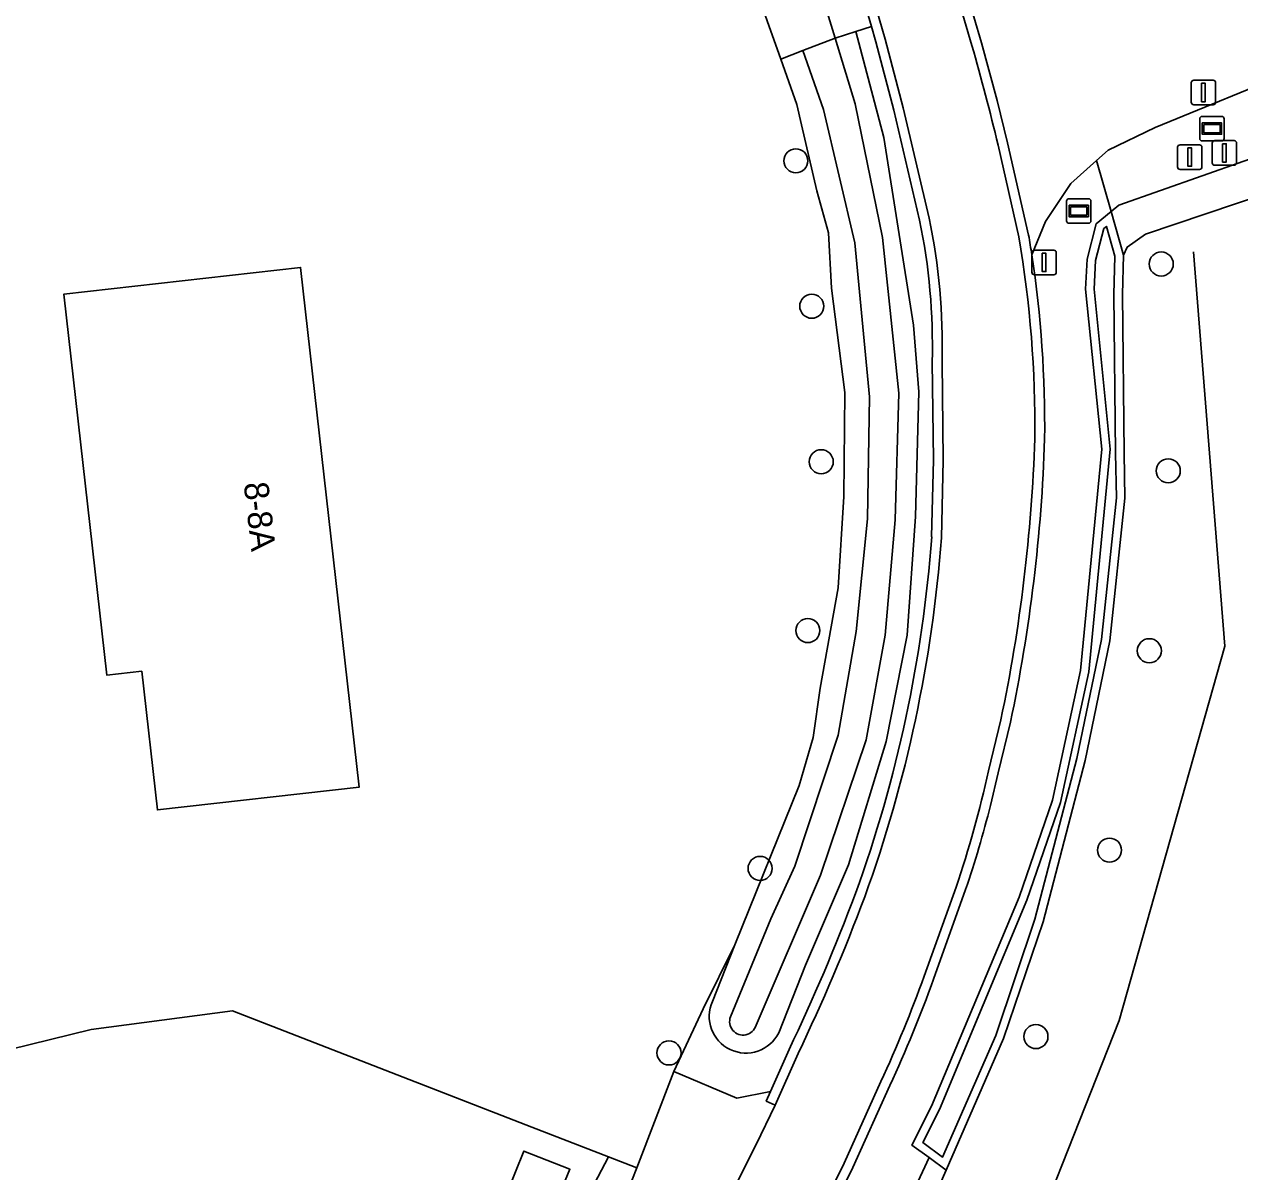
# Model space of a CAD drawing. Extents: x 162510 to 163918, y 388494 to 389774.
# Drawn here: x 163242.06 to 163291.5, y 389283.89 to 389330.57 of the extents above; entities that cross this region are included whole.
import ezdxf

# ---------------------------------------------------------------- set-up
doc = ezdxf.new("R2010")
doc.units = 0
for name, color, linetype in [('IMGEO_Afsluitpaal', 7, 'Continuous'), ('IMGEO_Boom', 7, 'Continuous'), ('IMGEO_Duiker', 7, 'Continuous'), ('IMGEO_Erf', 7, 'Continuous'), ('IMGEO_Grasland_agrarisch', 7, 'Continuous'), ('IMGEO_Grasland_overig', 7, 'Continuous'), ('IMGEO_Hek', 7, 'Continuous'), ('IMGEO_Informatiebord', 7, 'Continuous'), ('IMGEO_Lichtmast', 7, 'Continuous'), ('IMGEO_Oever', 7, 'Continuous'), ('IMGEO_Pand', 7, 'Continuous'), ('IMGEO_Pand_nummerreeks', 7, 'Continuous'), ('IMGEO_Rijbaan_lokaal_gesloten', 7, 'Continuous'), ('IMGEO_Rijbaan_lokaal_halfverhard', 7, 'Continuous'), ('IMGEO_Rijbaan_lokaal_onverhard', 7, 'Continuous'), ('IMGEO_Waterloop', 7, 'Continuous'), ('IMGEO_Wegwijzer', 7, 'Continuous')]:
    doc.layers.add(name, color=color, linetype=linetype)

msp = doc.modelspace()

# ---------------------------------------------------------------- linework, layer by layer
at = {"layer": 'IMGEO_Afsluitpaal'}
for p, q in [((163289.633, 389328.291), (163290.423, 389328.291)), ((163290.423, 389328.291), (163289.633, 389328.291)), ((163289.533, 389327.391), (163289.533, 389328.191)), ((163289.533, 389328.191), (163289.533, 389327.391)), ((163290.523, 389328.191), (163290.523, 389327.391)), ((163290.523, 389327.391), (163290.523, 389328.191)), ((163290.423, 389327.291), (163289.633, 389327.291)), ((163289.633, 389327.291), (163290.423, 389327.291)), ((163290.485, 389325.832), (163291.275, 389325.832)), ((163291.275, 389325.832), (163290.485, 389325.832)), ((163288.975, 389324.762), (163288.975, 389325.562)), ((163288.975, 389325.562), (163288.975, 389324.762)), ((163289.075, 389325.662), (163289.865, 389325.662)), ((163289.865, 389325.662), (163289.075, 389325.662)), ((163289.965, 389325.562), (163289.965, 389324.762)), ((163289.965, 389324.762), (163289.965, 389325.562)), ((163290.385, 389324.932), (163290.385, 389325.732)), ((163290.385, 389325.732), (163290.385, 389324.932)), ((163291.375, 389325.732), (163291.375, 389324.932)), ((163291.375, 389324.932), (163291.375, 389325.732)), ((163291.275, 389324.832), (163290.485, 389324.832)), ((163290.485, 389324.832), (163291.275, 389324.832)), ((163289.865, 389324.662), (163289.075, 389324.662)), ((163289.075, 389324.662), (163289.865, 389324.662))]:
    msp.add_line(p, q, dxfattribs=at)
for points in [[(163289.953, 389328.166), (163290.103, 389328.166), (163290.103, 389327.416), (163289.953, 389327.416), (163289.953, 389328.166)], [(163289.395, 389325.537), (163289.545, 389325.537), (163289.545, 389324.787), (163289.395, 389324.787), (163289.395, 389325.537)], [(163290.805, 389325.707), (163290.955, 389325.707), (163290.955, 389324.957), (163290.805, 389324.957), (163290.805, 389325.707)]]:
    msp.add_lwpolyline(points, dxfattribs=at)
for centre, start, end in [((163289.633, 389328.191), 90, 180), ((163289.633, 389328.191), 90, 180), ((163290.423, 389328.191), 0, 90), ((163290.423, 389328.191), 360, 90), ((163289.633, 389327.391), 180, 270), ((163289.633, 389327.391), 180, 270), ((163290.423, 389327.391), 270, 0), ((163290.423, 389327.391), 270, 0), ((163290.485, 389325.732), 90, 180), ((163290.485, 389325.732), 90, 180), ((163291.275, 389325.732), 0, 90), ((163291.275, 389325.732), 360, 90), ((163289.075, 389325.562), 90, 180), ((163289.075, 389325.562), 90, 180), ((163289.865, 389325.562), 0, 90), ((163289.865, 389325.562), 360, 90), ((163290.485, 389324.932), 180, 270), ((163290.485, 389324.932), 180, 270), ((163291.275, 389324.932), 270, 0), ((163291.275, 389324.932), 270, 0), ((163289.075, 389324.762), 180, 270), ((163289.075, 389324.762), 180, 270), ((163289.865, 389324.762), 270, 0), ((163289.865, 389324.762), 270, 0)]:
    msp.add_arc(centre, 0.1, start, end, dxfattribs=at)
at = {"layer": 'IMGEO_Boom'}
for centre in [(163273.447, 389325.011), (163288.31, 389320.814), (163274.093, 389319.095), (163274.479, 389312.769), (163288.596, 389312.401), (163273.936, 389305.901), (163287.825, 389305.08), (163286.207, 389296.968), (163271.992, 389296.225), (163283.213, 389289.383), (163268.286, 389288.718)]:
    msp.add_circle(centre, 0.489, dxfattribs=at)
at = {"layer": 'IMGEO_Duiker'}
msp.add_lwpolyline([(163278.867, 389284.457), (163277.326, 389281.143)], dxfattribs=at)
at = {"layer": 'IMGEO_Erf'}
msp.add_lwpolyline([(163232.301, 389286.601), (163244.784, 389289.669), (163250.529, 389290.428), (163262.709, 389285.696), (163265.823, 389284.486), (163266.976, 389284.038), (163268.487, 389287.957), (163269.683, 389290.516), (163270.969, 389293.119), (163273.587, 389299.602), (163274.156, 389301.55), (163274.434, 389303.56), (163275.172, 389307.633), (163275.403, 389311.36), (163275.434, 389315.58), (163274.898, 389319.829), (163274.772, 389322.079), (163274.299, 389323.795), (163273.681, 389326.482), (163273.492, 389327.306), (163272.836, 389329.151), (163269.924, 389337.342)], dxfattribs=at)
msp.add_lwpolyline([(163246.84, 389304.243), (163245.419, 389304.083), (163243.674, 389319.589), (163253.298, 389320.673), (163255.677, 389299.526), (163247.474, 389298.603)], close=True, dxfattribs=at)
at = {"layer": 'IMGEO_Grasland_agrarisch'}
for points in [[(163212.619, 389258.208), (163234.077, 389262.521), (163248.477, 389263.434), (163254.518, 389263.478), (163256.243, 389266.221), (163265.823, 389284.486), (163262.709, 389285.696), (163250.529, 389290.428), (163244.784, 389289.669), (163232.301, 389286.601), (163231.473, 389290.665), (163191.729, 389283.182), (163190.743, 389261.583), (163198.097, 389256.412)], [(163261.7, 389283.04), (163262.382, 389284.726), (163264.257, 389283.987), (163263.565, 389282.302)]]:
    msp.add_lwpolyline(points, close=True, dxfattribs=at)
at = {"layer": 'IMGEO_Grasland_overig'}
for points in [[(163234.4, 389380.748), (163244.974, 389373.164), (163249.614, 389369.491), (163252.271, 389366.973), (163253.383, 389365.918), (163256.212, 389363.237), (163261.491, 389357.147), (163265.728, 389350.914), (163268.579, 389345.937), (163270.698, 389341.576), (163273.979, 389333.498), (163275.043, 389330.003), (163275.89, 389330.272), (163276.518, 389330.471), (163275.79, 389332.99)], [(163307.527, 389333.427), (163293.822, 389328.725), (163288.061, 389326.364), (163286.148, 389325.442), (163285.682, 389325.023), (163286.269, 389322.944), (163286.586, 389323.203), (163303.528, 389329.172), (163330.75, 389337.384)], [(163317.163, 389331.716), (163302.442, 389326.998), (163287.667, 389322.026), (163286.926, 389321.499), (163286.771, 389321.17), (163286.731, 389319.571), (163286.801, 389313.121), (163286.835, 389311.292), (163286.225, 389305.483), (163285.216, 389300.617), (163283.506, 389294.054), (163281.898, 389289.299), (163279.562, 389283.949), (163278.174, 389280.815), (163276.118, 389276.569), (163281.728, 389277.718), (163284.586, 389278.304), (163301.946, 389282.821), (163313.304, 389286.249), (163313.894, 389286.904), (163315.707, 389288.056), (163317.926, 389289.052), (163322.028, 389290.564), (163369.306, 389307.211)], [(163276.518, 389330.471), (163275.89, 389330.272), (163277.029, 389325.96), (163278.23, 389318.321), (163278.445, 389315.608), (163278.319, 389310.538), (163277.974, 389305.718), (163277.123, 389301.392), (163275.583, 389296.37), (163273.841, 389292.295), (163272.748, 389289.538)], [(163278.48, 389322.603), (163277.427, 389327.076), (163276.695, 389329.857), (163276.518, 389330.471)], [(163279.562, 389283.949), (163278.867, 389284.457), (163278.164, 389284.972), (163278.97, 389286.555), (163282.525, 389295.055), (163283.881, 389299.004), (163285.02, 389304.275), (163285.888, 389313.281), (163285.235, 389319.787), (163285.296, 389321.006), (163285.665, 389322.45), (163286.269, 389322.944), (163285.682, 389325.023), (163284.638, 389324.084), (163283.608, 389322.544), (163283.044, 389321.189)], [(163278.971, 389309.709), (163279.04, 389312.842), (163278.994, 389316.835)], [(163282.174, 389302.17), (163281.671, 389300.117), (163281.362, 389298.788)], [(163280.353, 389295.366), (163279.051, 389291.716)], [(163270.053, 389290.816), (163270.969, 389293.119), (163269.683, 389290.516), (163268.487, 389287.957), (163271.048, 389286.878), (163272.414, 389287.143), (163273.172, 389288.855)], [(163277.272, 389287.387), (163275.765, 389284.057), (163274.152, 389280.802), (163272.578, 389277.643), (163271.775, 389276.032), (163269.509, 389270.677), (163268.641, 389268.501)], [(163269.436, 389231.236), (163268.414, 389236.273), (163267.223, 389245.043), (163266.904, 389250), (163266.888, 389253.095), (163267.485, 389260.25), (163267.991, 389262.937), (163269.925, 389269.014), (163270.564, 389269.289), (163270.582, 389268.678), (163274.085, 389275.054), (163273.887, 389275.255), (163273.665, 389275.481), (163273.8, 389276.394), (163275.222, 389279.189), (163276.399, 389281.501), (163277.326, 389281.143), (163278.174, 389280.815), (163279.562, 389283.949)]]:
    msp.add_lwpolyline(points, dxfattribs=at)
msp.add_lwpolyline([(163206.52, 389253.451), (163234.719, 389258.866), (163254.945, 389259.651), (163256.249, 389259.675), (163256.407, 389260.628), (163256.969, 389262.897), (163259.652, 389270.003), (163263.297, 389277.144), (163265.424, 389281.052), (163266.781, 389283.531), (163266.976, 389284.038), (163265.823, 389284.486), (163256.243, 389266.221), (163254.518, 389263.478), (163248.477, 389263.434), (163234.077, 389262.521), (163212.619, 389258.208), (163193.402, 389254.345), (163194.216, 389249.018)], close=True, dxfattribs=at)
for centre, radius, start, end in [((163253.743, 389317.492), 25.259, 358.5101, 11.6745), ((163237.224, 389314.232), 46.345, 359.3405, 8.6329), ((163217.157, 389315.869), 66.445, 348.10223, 358.12875), ((163224.671, 389313.727), 54.449, 340.1178, 355.7677), ((163240.155, 389309.078), 42.472, 341.1643, 345.9786), ((163201.52, 389323.072), 79.403, 334.47366, 339.45818), ((163224.341, 389311.669), 58.235, 335.3568, 339.96284), ((163271.414, 389290.205), 1.492, 155.8214, 333.4369)]:
    msp.add_arc(centre, radius, start, end, dxfattribs=at)
at = {"layer": 'IMGEO_Hek'}
msp.add_lwpolyline([(163281.728, 389277.718), (163286.594, 389290.034), (163290.895, 389305.272), (163289.62, 389321.304)], dxfattribs=at)
at = {"layer": 'IMGEO_Informatiebord'}
for p, q in [((163289.977, 389326.821), (163290.767, 389326.821)), ((163290.767, 389326.821), (163289.977, 389326.821)), ((163289.877, 389325.921), (163289.877, 389326.721)), ((163289.877, 389326.721), (163289.877, 389325.921)), ((163290.867, 389326.721), (163290.867, 389325.921)), ((163290.867, 389325.921), (163290.867, 389326.721)), ((163290.767, 389325.821), (163289.977, 389325.821)), ((163289.977, 389325.821), (163290.767, 389325.821))]:
    msp.add_line(p, q, dxfattribs=at)
for points in [[(163289.978, 389326.553), (163290.766, 389326.553), (163290.766, 389326.089), (163289.978, 389326.089), (163289.978, 389326.553)], [(163290.043, 389326.488), (163290.043, 389326.154), (163290.701, 389326.154), (163290.701, 389326.488), (163290.043, 389326.488)]]:
    msp.add_lwpolyline(points, dxfattribs=at)
for centre, start, end in [((163289.977, 389326.721), 90, 180), ((163289.977, 389326.721), 90, 180), ((163290.767, 389326.721), 0, 90), ((163290.767, 389326.721), 360, 90), ((163289.977, 389325.921), 180, 270), ((163289.977, 389325.921), 180, 270), ((163290.767, 389325.921), 270, 0), ((163290.767, 389325.921), 270, 0)]:
    msp.add_arc(centre, 0.1, start, end, dxfattribs=at)
at = {"layer": 'IMGEO_Lichtmast'}
for p, q in [((163283.148, 389321.377), (163283.938, 389321.377)), ((163283.938, 389321.377), (163283.148, 389321.377)), ((163283.048, 389320.477), (163283.048, 389321.277)), ((163283.048, 389321.277), (163283.048, 389320.477)), ((163284.038, 389321.277), (163284.038, 389320.477)), ((163284.038, 389320.477), (163284.038, 389321.277)), ((163283.938, 389320.377), (163283.148, 389320.377)), ((163283.148, 389320.377), (163283.938, 389320.377))]:
    msp.add_line(p, q, dxfattribs=at)
msp.add_lwpolyline([(163283.468, 389321.252), (163283.618, 389321.252), (163283.618, 389320.502), (163283.468, 389320.502), (163283.468, 389321.252)], dxfattribs=at)
for centre, start, end in [((163283.148, 389321.277), 90, 180), ((163283.148, 389321.277), 90, 180), ((163283.938, 389321.277), 0, 90), ((163283.938, 389321.277), 360, 90), ((163283.148, 389320.477), 180, 270), ((163283.148, 389320.477), 180, 270), ((163283.938, 389320.477), 270, 0), ((163283.938, 389320.477), 270, 0)]:
    msp.add_arc(centre, 0.1, start, end, dxfattribs=at)
at = {"layer": 'IMGEO_Oever'}
for points in [[(163272.748, 389289.538), (163273.841, 389292.295), (163275.583, 389296.37), (163277.123, 389301.392), (163277.974, 389305.718), (163278.319, 389310.538), (163278.445, 389315.608), (163278.23, 389318.321), (163277.029, 389325.96), (163275.89, 389330.272), (163275.043, 389330.003), (163275.854, 389327.336), (163276.974, 389321.892), (163277.629, 389315.564), (163277.481, 389310.411), (163277.084, 389305.717), (163276.309, 389301.458), (163274.447, 389295.943), (163271.828, 389289.844)], [(163275.843, 389321.672), (163274.57, 389327.093), (163273.73, 389329.496), (163272.836, 389329.151), (163273.492, 389327.306), (163273.681, 389326.482), (163274.299, 389323.795), (163274.772, 389322.079), (163274.898, 389319.829), (163275.434, 389315.58), (163275.403, 389311.36), (163275.172, 389307.633), (163274.434, 389303.56), (163274.156, 389301.55), (163273.587, 389299.602), (163270.969, 389293.119), (163270.053, 389290.816)], [(163270.789, 389290.192), (163272.434, 389294.177), (163273.399, 389296.313), (163275.165, 389301.651), (163275.904, 389305.861), (163276.356, 389310.44), (163276.438, 389315.409), (163275.843, 389321.672)]]:
    msp.add_lwpolyline(points, dxfattribs=at)
for points in [[(163281.898, 389289.299), (163283.506, 389294.054), (163285.216, 389300.617), (163286.225, 389305.483), (163286.835, 389311.292), (163286.801, 389313.121), (163286.731, 389319.571), (163286.771, 389321.17), (163286.269, 389322.944), (163285.665, 389322.45), (163285.296, 389321.006), (163285.235, 389319.787), (163285.888, 389313.281), (163285.02, 389304.275), (163283.881, 389299.004), (163282.525, 389295.055), (163278.97, 389286.555), (163278.164, 389284.972), (163278.867, 389284.457), (163279.562, 389283.949)], [(163286.385, 389319.573), (163286.455, 389313.116), (163286.489, 389311.307), (163285.883, 389305.536), (163284.879, 389300.696), (163283.174, 389294.153), (163281.575, 389289.424), (163279.418, 389284.483), (163278.606, 389285.077), (163279.284, 389286.41), (163282.849, 389294.932), (163284.215, 389298.911), (163285.362, 389304.222), (163286.236, 389313.282), (163285.582, 389319.796), (163285.64, 389320.954), (163285.972, 389322.254), (163286.08, 389322.342), (163286.424, 389321.126)]]:
    msp.add_lwpolyline(points, close=True, dxfattribs=at)
for centre, radius, start, end in [((163271.414, 389290.205), 1.492, 155.8214, 333.4369), ((163271.3, 389289.993), 0.548, 158.7378, 344.227)]:
    msp.add_arc(centre, radius, start, end, dxfattribs=at)
at = {"layer": 'IMGEO_Pand'}
for points in [[(163247.474, 389298.603), (163255.677, 389299.526), (163253.298, 389320.673), (163243.674, 389319.589), (163245.419, 389304.083), (163246.84, 389304.243)], [(163263.565, 389282.302), (163264.257, 389283.987), (163262.382, 389284.726), (163261.7, 389283.04)]]:
    msp.add_lwpolyline(points, close=True, dxfattribs=at)
at = {"layer": 'IMGEO_Rijbaan_lokaal_gesloten'}
for points in [[(163280.611, 389329.701), (163279.547, 389333.324)], [(163276.174, 389333.101), (163277.082, 389329.959), (163277.816, 389327.168), (163278.872, 389322.684)], [(163282.521, 389321.922), (163281.671, 389325.648)], [(163279.394, 389316.84), (163279.44, 389312.833), (163279.37, 389309.679)], [(163281.28, 389300.201), (163281.786, 389302.265)], [(163278.67, 389291.846), (163279.963, 389295.461)], [(163273.538, 389288.693), (163272.61, 389286.596), (163271.835, 389284.999), (163269.655, 389280.663), (163269.397, 389280.15), (163269.534, 389280.086), (163267.115, 389274.873), (163265.276, 389270.822), (163264.424, 389268.864), (163263.49, 389266.557)], [(163268.268, 389268.644), (163269.141, 389270.833), (163271.407, 389276.188), (163272.22, 389277.821), (163273.794, 389280.98), (163275.407, 389284.235), (163276.908, 389287.552)]]:
    msp.add_lwpolyline(points, dxfattribs=at)
for centre, radius, start, end in [((163198.179, 389305.977), 85.778, 13.25727, 16.05583), ((163253.676, 389317.488), 25.726, 358.5565, 11.652), ((163237.23, 389314.233), 45.939, 359.3496, 9.6346), ((163217.18, 389315.86), 66.02, 348.11637, 358.13532), ((163224.629, 389313.736), 54.891, 340.12, 355.7617), ((163240.035, 389309.108), 42.196, 341.1302, 347.8141), ((163201.561, 389323.057), 79.76, 334.47897, 339.45825), ((163225.176, 389311.288), 56.917, 335.3529, 340.0265)]:
    msp.add_arc(centre, radius, start, end, dxfattribs=at)
at = {"layer": 'IMGEO_Rijbaan_lokaal_halfverhard'}
for points in [[(163279.547, 389333.324), (163280.611, 389329.701)], [(163275.79, 389332.99), (163276.518, 389330.471), (163276.695, 389329.857), (163277.427, 389327.076), (163278.48, 389322.603)], [(163278.872, 389322.684), (163277.816, 389327.168), (163277.082, 389329.959), (163276.174, 389333.101)], [(163282.915, 389321.989), (163282.061, 389325.737), (163281.635, 389327.464), (163280.995, 389329.812), (163280.37, 389331.941)], [(163281.671, 389325.648), (163282.521, 389321.922)], [(163278.994, 389316.835), (163279.04, 389312.842), (163278.971, 389309.709)], [(163279.37, 389309.679), (163279.44, 389312.833), (163279.394, 389316.84)], [(163281.786, 389302.265), (163281.28, 389300.201)], [(163281.362, 389298.788), (163281.671, 389300.117), (163282.174, 389302.17)], [(163279.963, 389295.461), (163278.67, 389291.846)], [(163279.051, 389291.716), (163280.353, 389295.366)], [(163273.172, 389288.855), (163272.414, 389287.143), (163272.244, 389286.758), (163272.61, 389286.596), (163273.538, 389288.693)], [(163276.908, 389287.552), (163275.407, 389284.235), (163273.794, 389280.98), (163272.22, 389277.821), (163271.407, 389276.188), (163269.141, 389270.833), (163268.268, 389268.644)], [(163268.641, 389268.501), (163269.509, 389270.677), (163271.775, 389276.032), (163272.578, 389277.643), (163274.152, 389280.802), (163275.765, 389284.057), (163277.272, 389287.387)]]:
    msp.add_lwpolyline(points, dxfattribs=at)
msp.add_lwpolyline([(163272.61, 389286.596), (163272.244, 389286.758), (163272.414, 389287.143), (163271.048, 389286.878), (163268.487, 389287.957), (163266.976, 389284.038), (163266.781, 389283.531), (163269.505, 389282.07), (163269.655, 389280.663), (163271.835, 389284.999)], close=True, dxfattribs=at)
for centre, radius, start, end in [((163198.179, 389305.977), 85.778, 13.25727, 16.05583), ((163253.743, 389317.492), 25.259, 358.5101, 11.6745), ((163253.676, 389317.488), 25.726, 358.5565, 11.652), ((163237.23, 389314.233), 45.939, 359.3496, 9.6346), ((163228.26, 389312.766), 55.428, 8.7413, 9.5789), ((163237.224, 389314.232), 46.345, 359.3405, 8.6329), ((163217.18, 389315.86), 66.02, 348.11637, 358.13532), ((163217.157, 389315.869), 66.445, 348.10223, 358.12875), ((163224.671, 389313.727), 54.449, 340.1178, 355.7677), ((163224.629, 389313.736), 54.891, 340.12, 355.7617), ((163240.035, 389309.108), 42.196, 341.1302, 347.8141), ((163240.155, 389309.078), 42.472, 341.1643, 345.9786), ((163201.52, 389323.072), 79.403, 334.47366, 339.45818), ((163201.561, 389323.057), 79.76, 334.47897, 339.45825), ((163225.176, 389311.288), 56.917, 335.3529, 340.0265), ((163224.341, 389311.669), 58.235, 335.3568, 339.96284)]:
    msp.add_arc(centre, radius, start, end, dxfattribs=at)
at = {"layer": 'IMGEO_Rijbaan_lokaal_onverhard'}
for points in [[(163283.044, 389321.189), (163283.608, 389322.544), (163284.638, 389324.084), (163285.682, 389325.023), (163286.148, 389325.442), (163288.061, 389326.364), (163293.822, 389328.725), (163307.527, 389333.427), (163340.689, 389344.126), (163351.08, 389347.334), (163357.241, 389348.993), (163367.847, 389352.452), (163384.136, 389357.253)], [(163280.37, 389331.941), (163280.995, 389329.812), (163281.635, 389327.464), (163282.061, 389325.737), (163282.915, 389321.989)]]:
    msp.add_lwpolyline(points, dxfattribs=at)
msp.add_arc((163228.26, 389312.766), 55.428, 8.7413, 9.5789, dxfattribs=at)
at = {"layer": 'IMGEO_Waterloop'}
for points in [[(163227.822, 389357.879), (163254.484, 389363.075), (163257.497, 389359.265), (163260.257, 389355.431), (163267.208, 389343.156), (163269.924, 389337.342), (163272.836, 389329.151), (163273.73, 389329.496), (163275.043, 389330.003), (163273.979, 389333.498), (163270.698, 389341.576), (163268.579, 389345.937), (163265.728, 389350.914), (163261.491, 389357.147), (163256.212, 389363.237), (163253.383, 389365.918), (163252.271, 389366.973), (163249.614, 389369.491), (163244.974, 389373.164), (163234.4, 389380.748)], [(163275.854, 389327.336), (163275.043, 389330.003), (163273.73, 389329.496), (163274.57, 389327.093), (163275.843, 389321.672), (163276.438, 389315.409), (163276.356, 389310.44), (163275.904, 389305.861), (163275.165, 389301.651), (163273.399, 389296.313), (163272.434, 389294.177), (163270.789, 389290.192)], [(163271.828, 389289.844), (163274.447, 389295.943), (163276.309, 389301.458), (163277.084, 389305.717), (163277.481, 389310.411), (163277.629, 389315.564), (163276.974, 389321.892), (163275.854, 389327.336)]]:
    msp.add_lwpolyline(points, dxfattribs=at)
for points in [[(163286.771, 389321.17), (163286.926, 389321.499), (163287.667, 389322.026), (163302.442, 389326.998), (163317.163, 389331.716), (163330.685, 389335.811), (163354.525, 389343.444), (163354.831, 389343.619), (163355.037, 389343.973), (163354.839, 389344.558), (163354.206, 389344.716), (163353.264, 389344.522), (163330.75, 389337.384), (163303.528, 389329.172), (163286.586, 389323.203), (163286.269, 389322.944)], [(163286.385, 389319.573), (163286.424, 389321.126), (163286.08, 389322.342), (163285.972, 389322.254), (163285.64, 389320.954), (163285.582, 389319.796), (163286.236, 389313.282), (163285.362, 389304.222), (163284.215, 389298.911), (163282.849, 389294.932), (163279.284, 389286.41), (163278.606, 389285.077), (163279.418, 389284.483), (163281.575, 389289.424), (163283.174, 389294.153), (163284.879, 389300.696), (163285.883, 389305.536), (163286.489, 389311.307), (163286.455, 389313.116)]]:
    msp.add_lwpolyline(points, close=True, dxfattribs=at)
msp.add_arc((163271.3, 389289.993), 0.548, 158.7378, 344.227, dxfattribs=at)
at = {"layer": 'IMGEO_Wegwijzer'}
for p, q in [((163284.458, 389322.569), (163284.458, 389323.369)), ((163284.458, 389323.369), (163284.458, 389322.569)), ((163284.558, 389323.469), (163285.348, 389323.469)), ((163285.348, 389323.469), (163284.558, 389323.469)), ((163285.448, 389323.369), (163285.448, 389322.569)), ((163285.448, 389322.569), (163285.448, 389323.369)), ((163285.348, 389322.469), (163284.558, 389322.469)), ((163284.558, 389322.469), (163285.348, 389322.469))]:
    msp.add_line(p, q, dxfattribs=at)
for points in [[(163284.559, 389323.201), (163285.347, 389323.201), (163285.347, 389322.737), (163284.559, 389322.737), (163284.559, 389323.201)], [(163284.624, 389323.136), (163284.624, 389322.802), (163285.282, 389322.802), (163285.282, 389323.136), (163284.624, 389323.136)]]:
    msp.add_lwpolyline(points, dxfattribs=at)
for centre, start, end in [((163284.558, 389323.369), 90, 180), ((163284.558, 389323.369), 90, 180), ((163285.348, 389323.369), 0, 90), ((163285.348, 389323.369), 360, 90), ((163284.558, 389322.569), 180, 270), ((163284.558, 389322.569), 180, 270), ((163285.348, 389322.569), 270, 0), ((163285.348, 389322.569), 270, 0)]:
    msp.add_arc(centre, 0.1, start, end, dxfattribs=at)

# ---------------------------------------------------------------- texts
at = {"layer": 'IMGEO_Pand_nummerreeks'}
msp.add_text('8-8A', height=1, rotation=276.4187, dxfattribs=at).set_placement((163250.985, 389311.894))

doc.saveas('drawing.dxf')
